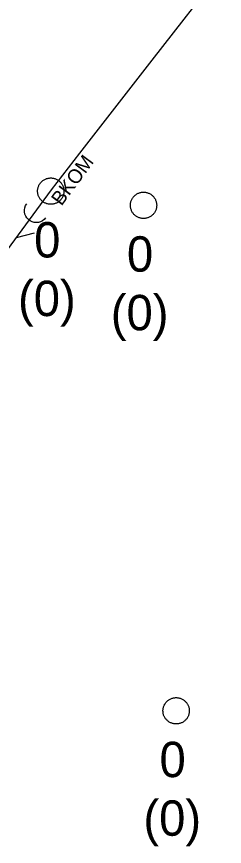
# Model space of a CAD drawing. Extents: x -606452 to -604459, y -1157823 to -1156972.
# Drawn here: x -605868.52 to -605864.58, y -1157441.63 to -1157425.89 of the extents above; entities that cross this region are included whole.
import ezdxf

# ---------------------------------------------------------------- set-up
doc = ezdxf.new("R2010")
doc.units = 0
doc.layers.add('Stoka', color=7, linetype='Continuous')
doc.layers.add('Vstupní šachta stoky', color=7, linetype='Continuous')

msp = doc.modelspace()

# ---------------------------------------------------------------- linework, layer by layer
at = {"layer": 'Stoka'}
for points in [[(-605865.949, -1157426.721), (-605864.577, -1157424.956)], [(-605867.321, -1157428.487), (-605865.949, -1157426.721)], [(-605867.86, -1157429.18), (-605867.321, -1157428.487)], [(-605869.189, -1157430.978), (-605867.86, -1157429.18)], [(-605867.972, -1157429.709), (-605868, -1157429.74), (-605868.032, -1157429.765), (-605868.069, -1157429.784), (-605868.109, -1157429.796), (-605868.15, -1157429.8), (-605868.191, -1157429.797), (-605868.23, -1157429.786), (-605868.268, -1157429.768), (-605868.301, -1157429.743), (-605868.329, -1157429.713), (-605868.351, -1157429.678), (-605868.366, -1157429.64), (-605868.374, -1157429.599), (-605868.375, -1157429.558), (-605868.368, -1157429.518), (-605868.353, -1157429.479), (-605868.332, -1157429.444)], [(-605868.524, -1157430.081), (-605868.185, -1157429.996)]]:
    msp.add_lwpolyline(points, dxfattribs=at)
at = {"layer": 'Vstupní šachta stoky'}
for p, q in [((-605867.888, -1157428.954), (-605867.875, -1157428.954)), ((-605866.126, -1157429.223), (-605866.113, -1157429.223)), ((-605865.507, -1157438.807), (-605865.494, -1157438.807))]:
    msp.add_line(p, q, dxfattribs=at)
for points in [[(-605867.875, -1157428.954), (-605867.862, -1157428.954), (-605867.849, -1157428.955), (-605867.836, -1157428.957), (-605867.823, -1157428.96), (-605867.81, -1157428.963), (-605867.797, -1157428.966), (-605867.785, -1157428.971), (-605867.773, -1157428.976), (-605867.761, -1157428.982), (-605867.749, -1157428.988), (-605867.738, -1157428.995), (-605867.727, -1157429.003), (-605867.717, -1157429.011), (-605867.707, -1157429.019), (-605867.697, -1157429.028), (-605867.688, -1157429.038), (-605867.68, -1157429.048), (-605867.672, -1157429.059), (-605867.664, -1157429.07), (-605867.657, -1157429.081), (-605867.651, -1157429.093), (-605867.646, -1157429.105), (-605867.641, -1157429.117), (-605867.636, -1157429.129), (-605867.633, -1157429.142), (-605867.63, -1157429.155), (-605867.628, -1157429.168), (-605867.626, -1157429.181), (-605867.625, -1157429.194), (-605867.625, -1157429.207), (-605867.626, -1157429.221), (-605867.627, -1157429.234), (-605867.629, -1157429.247), (-605867.631, -1157429.26), (-605867.635, -1157429.272), (-605867.638, -1157429.285), (-605867.643, -1157429.297), (-605867.648, -1157429.31), (-605867.654, -1157429.321), (-605867.661, -1157429.333), (-605867.668, -1157429.344), (-605867.675, -1157429.355), (-605867.684, -1157429.365), (-605867.692, -1157429.375), (-605867.702, -1157429.384), (-605867.712, -1157429.393), (-605867.722, -1157429.402), (-605867.732, -1157429.409), (-605867.743, -1157429.417), (-605867.755, -1157429.423), (-605867.767, -1157429.429), (-605867.779, -1157429.435), (-605867.791, -1157429.439), (-605867.803, -1157429.444), (-605867.816, -1157429.447), (-605867.829, -1157429.45), (-605867.842, -1157429.452), (-605867.855, -1157429.453), (-605867.868, -1157429.454), (-605867.882, -1157429.454), (-605867.895, -1157429.453), (-605867.908, -1157429.452), (-605867.921, -1157429.45), (-605867.934, -1157429.447), (-605867.947, -1157429.444), (-605867.959, -1157429.439), (-605867.971, -1157429.435), (-605867.983, -1157429.429), (-605867.995, -1157429.423), (-605868.007, -1157429.417), (-605868.018, -1157429.409), (-605868.028, -1157429.402), (-605868.038, -1157429.393), (-605868.048, -1157429.384), (-605868.058, -1157429.375), (-605868.066, -1157429.365), (-605868.075, -1157429.355), (-605868.082, -1157429.344), (-605868.089, -1157429.333), (-605868.096, -1157429.321), (-605868.102, -1157429.31), (-605868.107, -1157429.297), (-605868.112, -1157429.285), (-605868.115, -1157429.272), (-605868.119, -1157429.26), (-605868.121, -1157429.247), (-605868.123, -1157429.234), (-605868.124, -1157429.221), (-605868.125, -1157429.207), (-605868.125, -1157429.194), (-605868.124, -1157429.181), (-605868.122, -1157429.168), (-605868.12, -1157429.155), (-605868.117, -1157429.142), (-605868.114, -1157429.129), (-605868.109, -1157429.117), (-605868.104, -1157429.105), (-605868.099, -1157429.093), (-605868.093, -1157429.081), (-605868.086, -1157429.07)], [(-605868.086, -1157429.07), (-605868.078, -1157429.059), (-605868.07, -1157429.048), (-605868.062, -1157429.038), (-605868.053, -1157429.028), (-605868.043, -1157429.019), (-605868.033, -1157429.011), (-605868.023, -1157429.003), (-605868.012, -1157428.995), (-605868.001, -1157428.988), (-605867.989, -1157428.982), (-605867.977, -1157428.976), (-605867.965, -1157428.971), (-605867.953, -1157428.966), (-605867.94, -1157428.963), (-605867.927, -1157428.96), (-605867.914, -1157428.957), (-605867.901, -1157428.955), (-605867.888, -1157428.954)], [(-605866.113, -1157429.223), (-605866.1, -1157429.223), (-605866.087, -1157429.224), (-605866.074, -1157429.226), (-605866.061, -1157429.229), (-605866.048, -1157429.232), (-605866.035, -1157429.235), (-605866.023, -1157429.24), (-605866.011, -1157429.245), (-605865.999, -1157429.251), (-605865.987, -1157429.257), (-605865.976, -1157429.264), (-605865.965, -1157429.272), (-605865.955, -1157429.28), (-605865.945, -1157429.288), (-605865.935, -1157429.297), (-605865.926, -1157429.307), (-605865.918, -1157429.317), (-605865.91, -1157429.328), (-605865.902, -1157429.339), (-605865.895, -1157429.35), (-605865.889, -1157429.362), (-605865.884, -1157429.374), (-605865.879, -1157429.386), (-605865.874, -1157429.398), (-605865.871, -1157429.411), (-605865.868, -1157429.424), (-605865.866, -1157429.437), (-605865.864, -1157429.45), (-605865.863, -1157429.463), (-605865.863, -1157429.476), (-605865.864, -1157429.49), (-605865.865, -1157429.503), (-605865.867, -1157429.516), (-605865.869, -1157429.529), (-605865.873, -1157429.541), (-605865.876, -1157429.554), (-605865.881, -1157429.566), (-605865.886, -1157429.579), (-605865.892, -1157429.59), (-605865.899, -1157429.602), (-605865.906, -1157429.613), (-605865.913, -1157429.624), (-605865.922, -1157429.634), (-605865.93, -1157429.644), (-605865.94, -1157429.653), (-605865.95, -1157429.662), (-605865.96, -1157429.671), (-605865.97, -1157429.678), (-605865.981, -1157429.686), (-605865.993, -1157429.692), (-605866.005, -1157429.698), (-605866.017, -1157429.704), (-605866.029, -1157429.708), (-605866.041, -1157429.713), (-605866.054, -1157429.716), (-605866.067, -1157429.719), (-605866.08, -1157429.721), (-605866.093, -1157429.722), (-605866.106, -1157429.723), (-605866.12, -1157429.723), (-605866.133, -1157429.722), (-605866.146, -1157429.721), (-605866.159, -1157429.719), (-605866.172, -1157429.716), (-605866.185, -1157429.713), (-605866.197, -1157429.708), (-605866.209, -1157429.704), (-605866.221, -1157429.698), (-605866.233, -1157429.692), (-605866.245, -1157429.686), (-605866.256, -1157429.678), (-605866.266, -1157429.671), (-605866.276, -1157429.662), (-605866.286, -1157429.653), (-605866.296, -1157429.644), (-605866.304, -1157429.634), (-605866.313, -1157429.624), (-605866.32, -1157429.613), (-605866.327, -1157429.602), (-605866.334, -1157429.59), (-605866.34, -1157429.579), (-605866.345, -1157429.566), (-605866.35, -1157429.554), (-605866.353, -1157429.541), (-605866.357, -1157429.529), (-605866.359, -1157429.516), (-605866.361, -1157429.503), (-605866.362, -1157429.49), (-605866.363, -1157429.476), (-605866.363, -1157429.463), (-605866.362, -1157429.45), (-605866.36, -1157429.437), (-605866.358, -1157429.424), (-605866.355, -1157429.411), (-605866.352, -1157429.398), (-605866.347, -1157429.386), (-605866.342, -1157429.374), (-605866.337, -1157429.362), (-605866.331, -1157429.35), (-605866.324, -1157429.339)], [(-605866.324, -1157429.339), (-605866.316, -1157429.328), (-605866.308, -1157429.317), (-605866.3, -1157429.307), (-605866.291, -1157429.297), (-605866.281, -1157429.288), (-605866.271, -1157429.28), (-605866.261, -1157429.272), (-605866.25, -1157429.264), (-605866.239, -1157429.257), (-605866.227, -1157429.251), (-605866.215, -1157429.245), (-605866.203, -1157429.24), (-605866.191, -1157429.235), (-605866.178, -1157429.232), (-605866.165, -1157429.229), (-605866.152, -1157429.226), (-605866.139, -1157429.224), (-605866.126, -1157429.223)], [(-605865.494, -1157438.807), (-605865.481, -1157438.807), (-605865.468, -1157438.808), (-605865.455, -1157438.81), (-605865.442, -1157438.813), (-605865.429, -1157438.816), (-605865.416, -1157438.819), (-605865.404, -1157438.824), (-605865.392, -1157438.829), (-605865.38, -1157438.835), (-605865.368, -1157438.841), (-605865.357, -1157438.848), (-605865.346, -1157438.856), (-605865.336, -1157438.864), (-605865.326, -1157438.872), (-605865.316, -1157438.881), (-605865.307, -1157438.891), (-605865.299, -1157438.901), (-605865.291, -1157438.912), (-605865.283, -1157438.923), (-605865.276, -1157438.934), (-605865.27, -1157438.946), (-605865.265, -1157438.958), (-605865.26, -1157438.97), (-605865.255, -1157438.982), (-605865.252, -1157438.995), (-605865.249, -1157439.008), (-605865.247, -1157439.021), (-605865.245, -1157439.034), (-605865.244, -1157439.047), (-605865.244, -1157439.06), (-605865.245, -1157439.074), (-605865.246, -1157439.087), (-605865.248, -1157439.1), (-605865.25, -1157439.113), (-605865.254, -1157439.125), (-605865.257, -1157439.138), (-605865.262, -1157439.15), (-605865.267, -1157439.163), (-605865.273, -1157439.174), (-605865.28, -1157439.186), (-605865.287, -1157439.197), (-605865.294, -1157439.208), (-605865.303, -1157439.218), (-605865.311, -1157439.228), (-605865.321, -1157439.237), (-605865.331, -1157439.246), (-605865.341, -1157439.255), (-605865.351, -1157439.262), (-605865.362, -1157439.27), (-605865.374, -1157439.276), (-605865.386, -1157439.282), (-605865.398, -1157439.288), (-605865.41, -1157439.292), (-605865.422, -1157439.297), (-605865.435, -1157439.3), (-605865.448, -1157439.303), (-605865.461, -1157439.305), (-605865.474, -1157439.306), (-605865.487, -1157439.307), (-605865.501, -1157439.307), (-605865.514, -1157439.306), (-605865.527, -1157439.305), (-605865.54, -1157439.303), (-605865.553, -1157439.3), (-605865.566, -1157439.297), (-605865.578, -1157439.292), (-605865.59, -1157439.288), (-605865.602, -1157439.282), (-605865.614, -1157439.276), (-605865.626, -1157439.27), (-605865.637, -1157439.262), (-605865.647, -1157439.255), (-605865.657, -1157439.246), (-605865.667, -1157439.237), (-605865.677, -1157439.228), (-605865.685, -1157439.218), (-605865.694, -1157439.208), (-605865.701, -1157439.197), (-605865.708, -1157439.186), (-605865.715, -1157439.174), (-605865.721, -1157439.163), (-605865.726, -1157439.15), (-605865.731, -1157439.138), (-605865.734, -1157439.125), (-605865.738, -1157439.113), (-605865.74, -1157439.1), (-605865.742, -1157439.087), (-605865.743, -1157439.074), (-605865.744, -1157439.06), (-605865.744, -1157439.047), (-605865.743, -1157439.034), (-605865.741, -1157439.021), (-605865.739, -1157439.008), (-605865.736, -1157438.995), (-605865.733, -1157438.982), (-605865.728, -1157438.97), (-605865.723, -1157438.958), (-605865.718, -1157438.946), (-605865.712, -1157438.934), (-605865.705, -1157438.923)], [(-605865.705, -1157438.923), (-605865.697, -1157438.912), (-605865.689, -1157438.901), (-605865.681, -1157438.891), (-605865.672, -1157438.881), (-605865.662, -1157438.872), (-605865.652, -1157438.864), (-605865.642, -1157438.856), (-605865.631, -1157438.848), (-605865.62, -1157438.841), (-605865.608, -1157438.835), (-605865.596, -1157438.829), (-605865.584, -1157438.824), (-605865.572, -1157438.819), (-605865.559, -1157438.816), (-605865.546, -1157438.813), (-605865.533, -1157438.81), (-605865.52, -1157438.808), (-605865.507, -1157438.807)]]:
    msp.add_lwpolyline(points, dxfattribs=at)

# ---------------------------------------------------------------- texts
at = {"layer": 'Stoka'}
msp.add_text('BKOM', height=0.2683, rotation=53.5394, dxfattribs=at).set_placement((-605867.672, -1157429.497))
at = {"layer": 'Vstupní šachta stoky'}
for s, height, p in [('0', 0.671, (-605868.191, -1157430.462)), ('0', 0.671, (-605866.429, -1157430.731)), ('(0)', 0.6708, (-605868.497, -1157431.573)), ('(0)', 0.6708, (-605866.735, -1157431.842)), ('0', 0.671, (-605865.81, -1157440.315)), ('(0)', 0.6708, (-605866.116, -1157441.426))]:
    msp.add_text(s, height=height, dxfattribs=at).set_placement(p)

doc.saveas('drawing.dxf')
